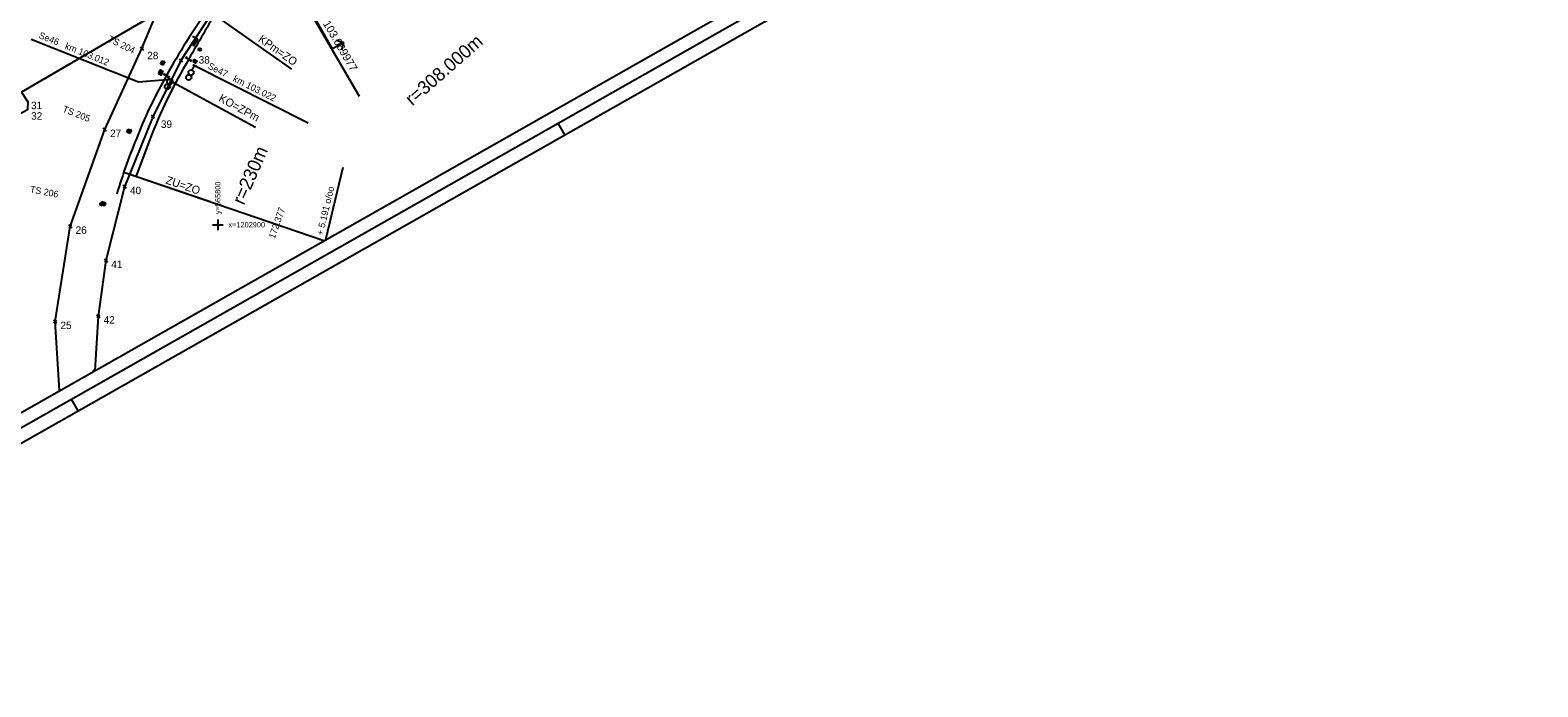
# Model space of a CAD drawing. Extents: x -566182 to -565305, y -1203073 to -1202401.
# Drawn here: x -565870 to -565305, y -1203073 to -1202827 of the extents above; entities that cross this region are included whole.
import ezdxf

# ---------------------------------------------------------------- set-up
doc = ezdxf.new("R2010")
doc.units = 0
for name, color, linetype in [('SZDC', 7, 'Continuous'), ('Vrstva 1', 7, 'Continuous'), ('Vrstva 10', 7, 'Continuous'), ('Vrstva 12', 7, 'Continuous'), ('Vrstva 13', 7, 'Continuous'), ('Vrstva 18', 7, 'Continuous'), ('Vrstva 22', 7, 'Continuous'), ('Vrstva 24', 7, 'Continuous'), ('Vrstva 25', 7, 'Continuous'), ('Vrstva 36', 7, 'Continuous'), ('Vrstva 39', 7, 'Continuous'), ('Vrstva 40', 7, 'Continuous'), ('Vrstva 5', 7, 'Continuous'), ('Vrstva 6', 7, 'Continuous'), ('Vrstva 60', 7, 'Continuous'), ('Vrstva 62', 7, 'Continuous')]:
    doc.layers.add(name, color=color, linetype=linetype)

# ---------------------------------------------------------------- blocks, each defined once
blk = doc.blocks.new('ODPOJ')
at = {"layer": 'Vrstva 62'}
blk.add_circle((0, 0), 5, dxfattribs=at)
blk = doc.blocks.new('C649')
at = {"layer": 'Vrstva 18'}
for p, q in [((-5, 10), (5, 10)), ((0, 10), (0, -10)), ((-5, -10), (5, -10))]:
    blk.add_line(p, q, dxfattribs=at)
blk = doc.blocks.new('C53')
at = {"layer": 'Vrstva 22'}
blk.add_line((-0.5, 0), (0.5, 0), dxfattribs=at)
blk.add_circle((0, 0), 5, dxfattribs=at)
blk = doc.blocks.new('C691')
at = {"layer": 'Vrstva 12'}
for p, q in [((-5, 0), (5, 0)), ((0, 5), (0, -5))]:
    blk.add_line(p, q, dxfattribs=at)
blk = doc.blocks.new('C661_2')
at = {"layer": 'Vrstva 12'}
for p, q in [((-5, 0.3), (-0.3, 5)), ((-5, -5), (5, 5)), ((0.3, -5), (5, -0.3))]:
    blk.add_line(p, q, dxfattribs=at)
blk.add_lwpolyline([(-5, 5), (5, 5), (5, -5), (-5, -5)], close=True, dxfattribs=at)
blk.add_lwpolyline([(-5, 5), (5, 5), (5, -5), (-5, -5), (-5, 5)], dxfattribs=at)
blk = doc.blocks.new('C673')
at = {"layer": 'Vrstva 36'}
for p, q in [((3.4, 8), (5.1, 9.7)), ((8.7, 8), (13, 12.3)), ((14, 8), (21, 15)), ((19.3, 8), (28.9, 17.6)), ((24.6, 8), (30, 13.4)), ((29.9, 8), (30, 8.1))]:
    blk.add_line(p, q, dxfattribs=at)
blk.add_lwpolyline([(0, 8), (30, 18), (30, 8)], close=True, dxfattribs=at)
blk.add_lwpolyline([(0, 8), (30, 18), (30, 8), (0, 8)], dxfattribs=at)
blk = doc.blocks.new('C575_6')
at = {"layer": 'Vrstva 24'}
blk.add_line((0, 10), (0, -10), dxfattribs=at)
for centre in [(10, 0), (30, 0)]:
    blk.add_circle(centre, 10, dxfattribs=at)
blk = doc.blocks.new('C569_5')
at = {"layer": 'Vrstva 24'}
for p, q in [((0, -7.5), (0, 7.5)), ((20, 0), (0, 0))]:
    blk.add_line(p, q, dxfattribs=at)
for centre in [(30, 0), (50, 0)]:
    blk.add_circle(centre, 10, dxfattribs=at)
blk = doc.blocks.new('STTRAN')
at = {"layer": 'Vrstva 40'}
for p, q in [((-5, 0), (5, 0)), ((0, 5), (0, -5))]:
    blk.add_line(p, q, dxfattribs=at)
blk.add_lwpolyline([(-5, 5), (5, 5), (5, -5), (-5, -5)], close=True, dxfattribs=at)
blk = doc.blocks.new('ODPOJ_1')
at = {"layer": 'Vrstva 40'}
blk.add_circle((0, 0), 5, dxfattribs=at)
blk = doc.blocks.new('C562')
at = {"layer": 'Vrstva 12'}
for p, q in [((-5, 0), (5, 0)), ((-4, -3), (-1, 0)), ((-0.6, -5), (4.3, 0))]:
    blk.add_line(p, q, dxfattribs=at)
blk.add_lwpolyline([(5, 0), (-5, 0)], dxfattribs=at)
blk.add_circle((0, 0), 5.03, dxfattribs=at)
blk.add_arc((0, 0), 5.03, 180, 0, dxfattribs=at)

msp = doc.modelspace()

# ---------------------------------------------------------------- linework, layer by layer
at = {"layer": 'SZDC'}
for p, q in [((-565800.65, -1202818.05), (-565813.8, -1202838.35)), ((-565813.8, -1202838.35), (-565824.38, -1202859.45)), ((-565824.38, -1202859.45), (-565834.96, -1202885.73)), ((-565834.96, -1202885.73), (-565841.98, -1202913.48)), ((-565841.98, -1202913.48), (-565844.83, -1202934.31)), ((-565844.83, -1202934.31), (-565846.16, -1202954.76))]:
    msp.add_line(p, q, dxfattribs=at)
msp.add_lwpolyline([(-565859.38, -1202962.26), (-565861.03, -1202936.37), (-565855.35, -1202900.62), (-565842.42, -1202864.28), (-565828.48, -1202833.86), (-565823.01, -1202820.65), (-565873.65, -1202850.2), (-565871.3, -1202853.81), (-565871.36, -1202856.88), (-565872.74, -1202857.66), (-566063.99, -1202965.17)], dxfattribs=at)
at = {"layer": 'Vrstva 1'}
for p, q in [((-565756.98, -1202834.01), (-565794.79, -1202767.36)), ((-565752.63, -1202831.54), (-565756.98, -1202834.01)), ((-565755.52, -1202830.74), (-565752.63, -1202831.54)), ((-565753.43, -1202834.43), (-565752.63, -1202831.54)), ((-565672.32, -1202861.89), (-565669.86, -1202866.23)), ((-565854.98, -1202965.51), (-565852.51, -1202969.86))]:
    msp.add_line(p, q, dxfattribs=at)
for points in [[(-566035.16, -1203073.47), (-565304.55, -1202658.99), (-565451.1, -1202400.68), (-566181.71, -1202815.16)], [(-565311.37, -1202657.11), (-566033.28, -1203066.66), (-566174.89, -1202817.04), (-565452.98, -1202407.49)], [(-566031.4, -1203059.85), (-565496.48, -1202756.39), (-565633.16, -1202515.46), (-566168.08, -1202818.92)]]:
    msp.add_lwpolyline(points, close=True, dxfattribs=at)
at = {"layer": 'Vrstva 10'}
for p, q in [((-565821.48, -1202839.61), (-565820.86, -1202838.46)), ((-565820.64, -1202840.1), (-565821.48, -1202839.61)), ((-565820.86, -1202838.46), (-565819.98, -1202838.95)), ((-565819.98, -1202838.95), (-565820.64, -1202840.1)), ((-565834.11, -1202865.3), (-565833.61, -1202864.11)), ((-565833.02, -1202865.73), (-565834.11, -1202865.3)), ((-565833.61, -1202864.11), (-565832.49, -1202864.52)), ((-565832.49, -1202864.52), (-565833.02, -1202865.73)), ((-565843.7, -1202892.47), (-565843.39, -1202891.3)), ((-565843.39, -1202891.3), (-565842.09, -1202891.74)), ((-565842.09, -1202891.74), (-565842.43, -1202892.85)), ((-565842.43, -1202892.85), (-565843.7, -1202892.47))]:
    msp.add_line(p, q, dxfattribs=at)
msp.add_lwpolyline([(-565807.65, -1202830.26), (-565809.43, -1202829.34)], dxfattribs=at)
at = {"layer": 'Vrstva 5'}
for p, q in [((-565802, -1202900), (-565798, -1202900)), ((-565800, -1202898), (-565800, -1202902))]:
    msp.add_line(p, q, dxfattribs=at)
at = {"layer": 'Vrstva 6'}
msp.add_lwpolyline([(-565825.52, -1202867.99), (-565830.68, -1202881.67)], dxfattribs=at)
for centre, radius, start, end in [((-565601.1, -1202963.58), 248.77, 144.5555, 151.2712), ((-565363.77, -1203087.21), 511.93, 148.3884, 150.8471), ((-565640.34, -1202939.41), 198.47, 149.2146, 158.9083), ((-565677.12, -1202926.28), 164.22, 149.9356, 158.5889), ((-565607.24, -1202958.64), 241.13, 157.4916, 163.0795)]:
    msp.add_arc(centre, radius, start, end, dxfattribs=at)
at = {"layer": 'Vrstva 60'}
for p, q in [((-565778.53, -1202797.34), (-565746.96, -1202851.71)), ((-565802.19, -1202820.58), (-565772.31, -1202841.56)), ((-565829.79, -1202846.51), (-565870.04, -1202830.5)), ((-565828.03, -1202834.31), (-565829.03, -1202833.31)), ((-565828.03, -1202833.41), (-565829.03, -1202834.41)), ((-565828.93, -1202834.31), (-565827.93, -1202833.31)), ((-565828.93, -1202833.41), (-565827.93, -1202834.41)), ((-565828.48, -1202833.86), (-565828.48, -1202833.86)), ((-565813.35, -1202838.8), (-565814.35, -1202837.8)), ((-565813.35, -1202837.9), (-565814.35, -1202838.9)), ((-565814.25, -1202838.8), (-565813.25, -1202837.8)), ((-565814.25, -1202837.9), (-565813.25, -1202838.9)), ((-565813.8, -1202838.35), (-565813.8, -1202838.35)), ((-565808.7, -1202840.2), (-565766.06, -1202861.71)), ((-565817.59, -1202845.49), (-565829.79, -1202846.51)), ((-565817.95, -1202845.84), (-565785.8, -1202863.33)), ((-565841.97, -1202864.73), (-565842.97, -1202863.73)), ((-565841.97, -1202863.83), (-565842.97, -1202864.83)), ((-565842.87, -1202864.73), (-565841.87, -1202863.73)), ((-565842.87, -1202863.83), (-565841.87, -1202864.83)), ((-565823.93, -1202859.9), (-565824.93, -1202858.9)), ((-565823.93, -1202859), (-565824.93, -1202860)), ((-565824.83, -1202859.9), (-565823.83, -1202858.9)), ((-565824.83, -1202859), (-565823.83, -1202860)), ((-565824.38, -1202859.45), (-565824.38, -1202859.45)), ((-565842.42, -1202864.28), (-565842.42, -1202864.28)), ((-565835.24, -1202880.22), (-565760.13, -1202905.96)), ((-565833.35, -1202880.86), (-565802.9, -1202891.3)), ((-565759.42, -1202905.55), (-565752.93, -1202878.35)), ((-565834.51, -1202886.18), (-565835.51, -1202885.18)), ((-565834.51, -1202885.28), (-565835.51, -1202886.28)), ((-565835.41, -1202886.18), (-565834.41, -1202885.18)), ((-565835.41, -1202885.28), (-565834.41, -1202886.28)), ((-565834.96, -1202885.73), (-565834.96, -1202885.73)), ((-565854.9, -1202901.07), (-565855.9, -1202900.07)), ((-565854.9, -1202900.17), (-565855.9, -1202901.17)), ((-565855.8, -1202901.07), (-565854.8, -1202900.07)), ((-565855.8, -1202900.17), (-565854.8, -1202901.17)), ((-565855.35, -1202900.62), (-565855.35, -1202900.62)), ((-565841.53, -1202913.93), (-565842.53, -1202912.93)), ((-565841.53, -1202913.03), (-565842.53, -1202914.03)), ((-565842.43, -1202913.93), (-565841.43, -1202912.93)), ((-565842.43, -1202913.03), (-565841.43, -1202914.03)), ((-565841.98, -1202913.48), (-565841.98, -1202913.48)), ((-565860.58, -1202936.82), (-565861.58, -1202935.82)), ((-565860.58, -1202935.92), (-565861.58, -1202936.92)), ((-565861.48, -1202936.82), (-565860.48, -1202935.82)), ((-565861.48, -1202935.92), (-565860.48, -1202936.92)), ((-565861.03, -1202936.37), (-565861.03, -1202936.37)), ((-565844.38, -1202934.76), (-565845.38, -1202933.76)), ((-565844.38, -1202933.86), (-565845.38, -1202934.86)), ((-565845.28, -1202934.76), (-565844.28, -1202933.76)), ((-565845.28, -1202933.86), (-565844.28, -1202934.86)), ((-565844.83, -1202934.31), (-565844.83, -1202934.31)), ((-565846.43, -1202954.91), (-565846.74, -1202954.6)), ((-565846.64, -1202954.7), (-565846.43, -1202954.91))]:
    msp.add_line(p, q, dxfattribs=at)

# ---------------------------------------------------------------- block references
at = {"layer": 'Vrstva 12', "xscale": 0.1, "yscale": 0.10000000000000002}
msp.add_blockref('C562', (-565820.73, -1202839.28), dxfattribs=at)
at = {"layer": 'Vrstva 12'}
for name, p, xscale, yscale, rotation in [('C691', (-565820.15, -1202838.91), 0.09999990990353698, 0.09999990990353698, 30.000029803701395), ('C691', (-565832.68, -1202864.56), 0.09999990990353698, 0.09999990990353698, 30.000029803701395), ('C661_2', (-565833.28, -1202864.86), 0.09999987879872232, 0.09999987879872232, 66.36215869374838), ('C661_2', (-565842.89, -1202892.07), 0.10000024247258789, 0.10000024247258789, 72.98811195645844)]:
    msp.add_blockref(name, p, dxfattribs=dict(at, xscale=xscale, yscale=yscale, rotation=rotation))
at = {"layer": 'Vrstva 18'}
for p, xscale, yscale, rotation in [((-565810.85, -1202837.83), 0.1000000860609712, 0.1000000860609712, 57.5711865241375), ((-565819.25, -1202844.01), 0.09999981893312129, 0.09999981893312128, 57.33338544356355)]:
    msp.add_blockref('C649', p, dxfattribs=dict(at, xscale=xscale, yscale=yscale, rotation=rotation))
at = {"layer": 'Vrstva 22', "xscale": 0.1, "yscale": 0.10000000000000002}
msp.add_blockref('C53', (-565806.76, -1202834.23), dxfattribs=at)
at = {"layer": 'Vrstva 24'}
for name, p, xscale, yscale, rotation in [('C569_5', (-565808.7, -1202840.2), 0.10000005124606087, 0.10000005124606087, -116.15375630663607), ('C575_6', (-565817.59, -1202845.49), 0.09999987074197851, 0.0999998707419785, -116.0103291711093)]:
    msp.add_blockref(name, p, dxfattribs=dict(at, xscale=xscale, yscale=yscale, rotation=rotation))
at = {"layer": 'Vrstva 36', "xscale": 0.09999995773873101, "yscale": 0.09999995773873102, "rotation": 61.95618673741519}
msp.add_blockref('C673', (-565808.35, -1202833.4), dxfattribs=at)
at = {"layer": 'Vrstva 40', "xscale": 0.10000002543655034, "yscale": 0.10000002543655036, "rotation": 59.3310546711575}
for p in [(-565808.53, -1202838.69), (-565821.6, -1202843.17), (-565821.26, -1202842.55)]:
    msp.add_blockref('STTRAN', p, dxfattribs=at)
at = {"layer": 'Vrstva 40', "xscale": 0.1, "yscale": 0.10000000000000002}
msp.add_blockref('ODPOJ_1', (-565843.6, -1202892.27), dxfattribs=at)
at = {"layer": 'Vrstva 62', "xscale": 0.1, "yscale": 0.10000000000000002}
msp.add_blockref('ODPOJ', (-565843.6, -1202892.27), dxfattribs=at)

# ---------------------------------------------------------------- texts
at = {"layer": 'Vrstva 13'}
for s, rotation, p in [('TS 204', 333.7835, (-565841.48, -1202831.11)), ('TS 205', 338.3446, (-565858.49, -1202857.51)), ('TS 206', 349.077, (-565870.65, -1202887.83))]:
    msp.add_text(s, height=2.5, rotation=rotation, dxfattribs=at).set_placement(p)
at = {"layer": 'Vrstva 25'}
for s, rotation, p in [('Se46   km 103.012', 337.8887, (-565867.41, -1202829.83)), ('Se47   km 103.022', 333.2247, (-565803.97, -1202841.22))]:
    msp.add_text(s, height=2.5, rotation=rotation, dxfattribs=at).set_placement(p)
at = {"layer": 'Vrstva 39'}
for s, height, rotation, p in [('ZO KM 103.069977', 3, 300.145, (-565767.57, -1202812.49)), ('KPm=ZO', 3, 324.928, (-565785.08, -1202830.97)), ('r=308.000m', 5, 41.328, (-565726.97, -1202855.59)), ('KO=ZPm', 3, 331.46, (-565799.94, -1202853.42)), ('r=230m', 5, 66.272, (-565790.22, -1202892.88)), ('ZU=ZO', 3, 341.085, (-565819.78, -1202884.46)), ('+ 5.191 o/oo', 2.5, 76.575, (-565760.56, -1202904.12)), ('172.377', 2.5, 71.085, (-565778.61, -1202905.46))]:
    msp.add_text(s, height=height, rotation=rotation, dxfattribs=at).set_placement(p)
at = {"layer": 'Vrstva 5'}
msp.add_text('y=565800', height=2, rotation=90, dxfattribs=at).set_placement((-565799, -1202896))
msp.add_text('x=1202900', height=2, dxfattribs=at).set_placement((-565796, -1202901))
at = {"layer": 'Vrstva 60'}
for s, p in [('28', (-565826.47, -1202837.88)), ('38', (-565807.17, -1202839.52)), ('31', (-565870.07, -1202856.61)), ('32', (-565870.05, -1202860.56)), ('39', (-565821.33, -1202863.63)), ('27', (-565840.41, -1202867.08)), ('40', (-565832.95, -1202888.53)), ('26', (-565853.34, -1202903.42)), ('41', (-565839.97, -1202916.28)), ('25', (-565859.02, -1202939.17)), ('42', (-565842.82, -1202937.11))]:
    msp.add_text(s, height=2.8, dxfattribs=at).set_placement(p)

doc.saveas('drawing.dxf')
